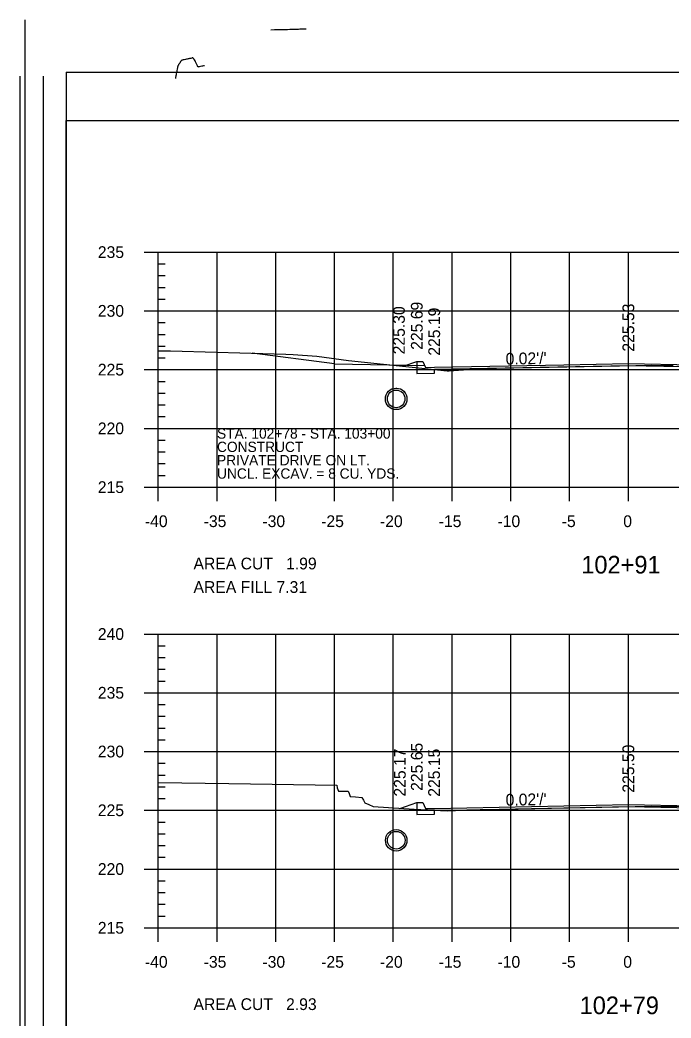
# Model space of a CAD drawing. Extents: x 1367903 to 1373764, y 376865 to 382130.
# Drawn here: x 1370213.6 to 1370324.4, y 377450.5 to 377620.4 of the extents above; entities that cross this region are included whole.
import ezdxf

# ---------------------------------------------------------------- set-up
doc = ezdxf.new("R2010")
doc.units = 0
for name, color, linetype in [('R_Axis', 7, 'Continuous'), ('R_Axis Annot', 7, 'Continuous'), ('R_Border', 7, 'Continuous'), ('R_Border PE', 7, 'Continuous'), ('R_Draft', 7, 'Continuous'), ('R_Drive', 7, 'Continuous'), ('R_Exist Surface', 7, 'Continuous'), ('R_Fin Surface', 7, 'Continuous'), ('R_Fin Surface Annot', 7, 'Continuous'), ('R_Grid', 7, 'Continuous'), ('R_Water', 7, 'Continuous')]:
    doc.layers.add(name, color=color, linetype=linetype)

msp = doc.modelspace()

# ---------------------------------------------------------------- linework, layer by layer
for points in [[(1370281.1, 377562.21), (1370281.1, 377561.54), (1370281.1, 377561.54), (1370281.1, 377560.18), (1370284.1, 377560.24), (1370284.1, 377560.91), (1370317.1, 377561.57), (1370350.1, 377560.91), (1370350.1, 377560.24), (1370353.1, 377560.18), (1370353.1, 377561.62), (1370367.1, 377561.9), (1370367.1, 377562.49)], [(1370281.1, 377487.14), (1370281.1, 377486.47), (1370281.1, 377486.47), (1370281.1, 377485.11), (1370284.1, 377485.17), (1370284.1, 377485.83), (1370317.1, 377486.49), (1370350.1, 377485.83), (1370350.1, 377485.17), (1370353.1, 377485.11), (1370353.1, 377486.55), (1370367.1, 377486.83), (1370367.1, 377487.42)]]:
    msp.add_lwpolyline(points)
at = {"layer": 'R_Axis'}
for p, q in [((1370234.7, 377580.84), (1370239.5, 377580.84)), ((1370237.1, 377540.84), (1370237.1, 377580.84)), ((1370237.1, 377578.84), (1370238.3, 377578.84)), ((1370237.1, 377576.84), (1370238.3, 377576.84)), ((1370237.1, 377574.84), (1370238.3, 377574.84)), ((1370237.1, 377572.84), (1370238.3, 377572.84)), ((1370234.7, 377570.84), (1370239.5, 377570.84)), ((1370237.1, 377568.84), (1370238.3, 377568.84)), ((1370237.1, 377566.84), (1370238.3, 377566.84)), ((1370237.1, 377564.84), (1370238.3, 377564.84)), ((1370237.1, 377562.84), (1370238.3, 377562.84)), ((1370234.7, 377560.84), (1370239.5, 377560.84)), ((1370237.1, 377558.84), (1370238.3, 377558.84)), ((1370237.1, 377556.84), (1370238.3, 377556.84)), ((1370237.1, 377554.84), (1370238.3, 377554.84)), ((1370237.1, 377552.84), (1370238.3, 377552.84)), ((1370234.7, 377550.84), (1370239.5, 377550.84)), ((1370237.1, 377548.84), (1370238.3, 377548.84)), ((1370237.1, 377546.84), (1370238.3, 377546.84)), ((1370237.1, 377544.84), (1370238.3, 377544.84)), ((1370237.1, 377538.44), (1370237.1, 377543.24)), ((1370237.1, 377542.84), (1370238.3, 377542.84)), ((1370247.1, 377538.44), (1370247.1, 377543.24)), ((1370257.1, 377538.44), (1370257.1, 377543.24)), ((1370267.1, 377538.44), (1370267.1, 377543.24)), ((1370277.1, 377538.44), (1370277.1, 377543.24)), ((1370287.1, 377538.44), (1370287.1, 377543.24)), ((1370297.1, 377538.44), (1370297.1, 377543.24)), ((1370307.1, 377538.44), (1370307.1, 377543.24)), ((1370317.1, 377538.44), (1370317.1, 377543.24)), ((1370234.7, 377540.84), (1370239.5, 377540.84)), ((1370237.1, 377540.84), (1370397.1, 377540.84)), ((1370234.7, 377515.84), (1370239.5, 377515.84)), ((1370237.1, 377465.84), (1370237.1, 377515.84)), ((1370237.1, 377513.84), (1370238.3, 377513.84)), ((1370237.1, 377511.84), (1370238.3, 377511.84)), ((1370237.1, 377509.84), (1370238.3, 377509.84)), ((1370237.1, 377507.84), (1370238.3, 377507.84)), ((1370234.7, 377505.84), (1370239.5, 377505.84)), ((1370237.1, 377503.84), (1370238.3, 377503.84)), ((1370237.1, 377501.84), (1370238.3, 377501.84)), ((1370237.1, 377499.84), (1370238.3, 377499.84)), ((1370237.1, 377497.84), (1370238.3, 377497.84)), ((1370234.7, 377495.84), (1370239.5, 377495.84)), ((1370237.1, 377493.84), (1370238.3, 377493.84)), ((1370237.1, 377491.84), (1370238.3, 377491.84)), ((1370237.1, 377489.84), (1370238.3, 377489.84)), ((1370237.1, 377487.84), (1370238.3, 377487.84)), ((1370234.7, 377485.84), (1370239.5, 377485.84)), ((1370237.1, 377483.84), (1370238.3, 377483.84)), ((1370237.1, 377481.84), (1370238.3, 377481.84)), ((1370237.1, 377479.84), (1370238.3, 377479.84)), ((1370237.1, 377477.84), (1370238.3, 377477.84)), ((1370234.7, 377475.84), (1370239.5, 377475.84)), ((1370237.1, 377473.84), (1370238.3, 377473.84)), ((1370237.1, 377471.84), (1370238.3, 377471.84)), ((1370237.1, 377469.84), (1370238.3, 377469.84)), ((1370237.1, 377463.44), (1370237.1, 377468.24)), ((1370237.1, 377467.84), (1370238.3, 377467.84)), ((1370247.1, 377463.44), (1370247.1, 377468.24)), ((1370257.1, 377463.44), (1370257.1, 377468.24)), ((1370267.1, 377463.44), (1370267.1, 377468.24)), ((1370277.1, 377463.44), (1370277.1, 377468.24)), ((1370287.1, 377463.44), (1370287.1, 377468.24)), ((1370297.1, 377463.44), (1370297.1, 377468.24)), ((1370307.1, 377463.44), (1370307.1, 377468.24)), ((1370317.1, 377463.44), (1370317.1, 377468.24)), ((1370234.7, 377465.84), (1370239.5, 377465.84)), ((1370237.1, 377465.84), (1370397.1, 377465.84))]:
    msp.add_line(p, q, dxfattribs=at)
at = {"layer": 'R_Border'}
for p, q in [((1370214.38, 377620.35), (1370214.38, 377279.12)), ((1370221.41, 377611.47), (1370425.73, 377611.47)), ((1370221.41, 377611.47), (1370221.41, 377280.59))]:
    msp.add_line(p, q, dxfattribs=at)
at = {"layer": 'R_Border PE'}
for p, q in [((1370213.57, 377610.76), (1370213.57, 377288.8)), ((1370217.49, 377610.76), (1370217.49, 377288.8)), ((1370221.41, 377603.25), (1370425.73, 377603.25)), ((1370221.41, 377288.8), (1370221.41, 377603.25))]:
    msp.add_line(p, q, dxfattribs=at)
for points in [[(1370258.26, 377618.69), (1370258.21, 377618.69), (1370257.93, 377618.68), (1370257.8, 377618.68), (1370257.73, 377618.67), (1370257.58, 377618.67), (1370257.22, 377618.66), (1370256.89, 377618.65), (1370256.26, 377618.63)], [(1370258.72, 377618.7), (1370258.26, 377618.69)], [(1370262.28, 377618.79), (1370261.93, 377618.78), (1370261.73, 377618.78), (1370261.57, 377618.77), (1370261.34, 377618.76), (1370261.19, 377618.76), (1370260.99, 377618.75), (1370260.74, 377618.75), (1370260.55, 377618.74), (1370260.27, 377618.73), (1370260.17, 377618.73), (1370260.12, 377618.73), (1370259.9, 377618.72), (1370259.8, 377618.72), (1370259.57, 377618.71), (1370259.49, 377618.72), (1370259.07, 377618.7), (1370258.83, 377618.7), (1370258.72, 377618.7)], [(1370244.96, 377612.54), (1370244.94, 377612.55), (1370244.92, 377612.55), (1370244.9, 377612.55), (1370244.88, 377612.55), (1370244.85, 377612.55), (1370244.83, 377612.55), (1370244.8, 377612.55), (1370244.66, 377612.51), (1370244.54, 377612.48), (1370244.27, 377612.41), (1370244.06, 377612.36), (1370244.03, 377612.35), (1370244.01, 377612.35), (1370243.99, 377612.34), (1370243.98, 377612.34), (1370243.97, 377612.35), (1370243.94, 377612.35), (1370243.92, 377612.36), (1370243.9, 377612.38), (1370243.88, 377612.39), (1370243.86, 377612.4), (1370243.84, 377612.42), (1370243.82, 377612.45), (1370243.81, 377612.47), (1370243.79, 377612.5), (1370243.77, 377612.55), (1370243.68, 377612.76), (1370243.57, 377613), (1370243.46, 377613.23), (1370243.45, 377613.26), (1370243.44, 377613.28), (1370243.4, 377613.34), (1370243.37, 377613.39), (1370243.25, 377613.57), (1370243.17, 377613.69), (1370243.14, 377613.74), (1370243.13, 377613.76), (1370243.11, 377613.78), (1370243.09, 377613.81), (1370243.07, 377613.83), (1370243.06, 377613.84), (1370243.04, 377613.85), (1370243.01, 377613.87), (1370243, 377613.87), (1370242.97, 377613.88), (1370242.94, 377613.88), (1370242.93, 377613.88), (1370242.89, 377613.88), (1370242.79, 377613.86), (1370242.62, 377613.82), (1370242.42, 377613.77), (1370242.28, 377613.74), (1370242.17, 377613.72), (1370242.03, 377613.69), (1370241.91, 377613.66), (1370241.74, 377613.63), (1370241.52, 377613.58), (1370241.47, 377613.57), (1370241.35, 377613.54), (1370241.23, 377613.52), (1370241.19, 377613.51), (1370241.16, 377613.5), (1370241.14, 377613.5), (1370241.13, 377613.49), (1370241.11, 377613.49), (1370241.09, 377613.47), (1370241.07, 377613.46), (1370241.05, 377613.44), (1370241.03, 377613.42), (1370241, 377613.39), (1370240.97, 377613.35), (1370240.94, 377613.31), (1370240.9, 377613.26), (1370240.84, 377613.16), (1370240.75, 377613.02), (1370240.67, 377612.89), (1370240.57, 377612.75), (1370240.52, 377612.67), (1370240.48, 377612.62), (1370240.45, 377612.55), (1370240.44, 377612.54), (1370240.43, 377612.52), (1370240.42, 377612.5), (1370240.41, 377612.48), (1370240.41, 377612.46), (1370240.4, 377612.44), (1370240.39, 377612.42), (1370240.39, 377612.39), (1370240.38, 377612.37), (1370240.38, 377612.35), (1370240.37, 377612.33), (1370240.36, 377612.24), (1370240.32, 377612), (1370240.27, 377611.76), (1370240.25, 377611.65), (1370240.17, 377611.18), (1370240.14, 377611.04), (1370240.1, 377610.84), (1370240.05, 377610.54), (1370240.02, 377610.39)]]:
    msp.add_lwpolyline(points, dxfattribs=at)
at = {"layer": 'R_Drive'}
for q in [(1370253.1, 377563.66), (1370282.44, 377561.54)]:
    msp.add_line((1370267.11, 377561.85), q, dxfattribs=at)
at = {"layer": 'R_Exist Surface'}
for points in [[(1370237.1, 377564.05), (1370239.21, 377564.02), (1370247.05, 377563.83), (1370258.81, 377563.49), (1370260.07, 377563.41), (1370264.09, 377563.14), (1370269.5, 377562.42), (1370286.24, 377560.66), (1370286.45, 377560.64), (1370286.56, 377560.64), (1370286.61, 377560.64), (1370289.82, 377560.88), (1370290.99, 377560.99), (1370291.65, 377561.04), (1370315.6, 377561.51), (1370321.08, 377561.61), (1370324.71, 377561.57)], [(1370237.1, 377490.54), (1370249.13, 377490.38), (1370267.48, 377490.09), (1370267.55, 377489.68), (1370267.77, 377489.1), (1370268.52, 377489.09), (1370269.4, 377489.07), (1370269.59, 377488.67), (1370269.74, 377488.18), (1370270.66, 377488.13), (1370271.74, 377488), (1370272.03, 377487.56), (1370272.27, 377487.1), (1370272.92, 377486.85), (1370273.66, 377486.46), (1370280.67, 377486.02), (1370286.26, 377485.74), (1370291.9, 377485.99), (1370292.12, 377485.99), (1370292.18, 377485.99), (1370292.28, 377485.99), (1370292.68, 377486), (1370321.12, 377486.53), (1370337.44, 377486.35)]]:
    msp.add_lwpolyline(points, dxfattribs=at)
at = {"layer": 'R_Fin Surface'}
for points in [[(1370278.8, 377561.44), (1370281.1, 377562.21), (1370282.1, 377562.21), (1370282.6, 377561.21), (1370284.1, 377561.24), (1370306.1, 377561.68), (1370317.1, 377561.9), (1370328.1, 377561.68), (1370350.1, 377561.24), (1370351.6, 377561.21), (1370352.1, 377562.21), (1370353.1, 377562.21), (1370357.1, 377562.29), (1370367.1, 377562.49), (1370374.27, 377560.1)], [(1370278.21, 377486.17), (1370281.1, 377487.14), (1370282.1, 377487.14), (1370282.6, 377486.14), (1370284.1, 377486.17), (1370306.1, 377486.61), (1370317.1, 377486.83), (1370328.1, 377486.61), (1370350.1, 377486.17), (1370351.6, 377486.14), (1370352.1, 377487.14), (1370353.1, 377487.14), (1370357.1, 377487.22), (1370367.1, 377487.42), (1370372.69, 377485.56)]]:
    msp.add_lwpolyline(points, dxfattribs=at)
at = {"layer": 'R_Grid'}
for p, q in [((1370237.1, 377580.84), (1370397.1, 377580.84)), ((1370237.1, 377540.84), (1370237.1, 377580.84)), ((1370247.1, 377540.84), (1370247.1, 377580.84)), ((1370257.1, 377540.84), (1370257.1, 377580.84)), ((1370267.1, 377540.84), (1370267.1, 377580.84)), ((1370277.1, 377540.84), (1370277.1, 377580.84)), ((1370287.1, 377540.84), (1370287.1, 377580.84)), ((1370297.1, 377540.84), (1370297.1, 377580.84)), ((1370307.1, 377540.84), (1370307.1, 377580.84)), ((1370317.1, 377540.84), (1370317.1, 377580.84)), ((1370237.1, 377570.84), (1370397.1, 377570.84)), ((1370237.1, 377560.84), (1370397.1, 377560.84)), ((1370237.1, 377550.84), (1370397.1, 377550.84)), ((1370237.1, 377540.84), (1370397.1, 377540.84)), ((1370237.1, 377515.84), (1370397.1, 377515.84)), ((1370237.1, 377465.84), (1370237.1, 377515.84)), ((1370247.1, 377465.84), (1370247.1, 377515.84)), ((1370257.1, 377465.84), (1370257.1, 377515.84)), ((1370267.1, 377465.84), (1370267.1, 377515.84)), ((1370277.1, 377465.84), (1370277.1, 377515.84)), ((1370287.1, 377465.84), (1370287.1, 377515.84)), ((1370297.1, 377465.84), (1370297.1, 377515.84)), ((1370307.1, 377465.84), (1370307.1, 377515.84)), ((1370317.1, 377465.84), (1370317.1, 377515.84)), ((1370237.1, 377505.84), (1370397.1, 377505.84)), ((1370237.1, 377495.84), (1370397.1, 377495.84)), ((1370237.1, 377485.84), (1370397.1, 377485.84)), ((1370237.1, 377475.84), (1370397.1, 377475.84)), ((1370237.1, 377465.84), (1370397.1, 377465.84))]:
    msp.add_line(p, q, dxfattribs=at)
at = {"layer": 'R_Water'}
for p, q in [((1370277.59, 377557.72), (1370277.59, 377557.67)), ((1370277.59, 377557.39), (1370277.59, 377557.34)), ((1370277.59, 377554.39), (1370277.59, 377554.34)), ((1370277.59, 377554.05), (1370277.59, 377554.01)), ((1370277.6, 377482.59), (1370277.6, 377482.54)), ((1370277.6, 377482.25), (1370277.6, 377482.21)), ((1370277.6, 377479.25), (1370277.6, 377479.21)), ((1370277.6, 377478.92), (1370277.6, 377478.87))]:
    msp.add_line(p, q, dxfattribs=at)
for centre, radius in [((1370277.59, 377555.86), 1.83), ((1370277.59, 377555.86), 1.5), ((1370277.6, 377480.73), 1.83), ((1370277.6, 377480.73), 1.5)]:
    msp.add_circle(centre, radius, dxfattribs=at)

# ---------------------------------------------------------------- texts
at = {"layer": 'R_Axis Annot'}
for s, height, p in [('235', 2, (1370226.82, 377579.84)), ('230', 2, (1370226.82, 377569.84)), ('225', 2, (1370226.82, 377559.84)), ('220', 2, (1370226.82, 377549.84)), ('215', 2, (1370226.82, 377539.84)), ('-40', 2, (1370234.83, 377534.04)), ('-35', 2, (1370244.83, 377534.04)), ('-30', 2, (1370254.83, 377534.04)), ('-25', 2, (1370264.83, 377534.04)), ('-20', 2, (1370274.83, 377534.04)), ('-15', 2, (1370284.83, 377534.04)), ('-10', 2, (1370294.83, 377534.04)), ('-5', 2, (1370305.76, 377534.04)), ('0', 2, (1370316.23, 377534.04)), ('AREA CUT   1.99', 2, (1370243.1, 377526.84)), ('102+91', 3, (1370309.09, 377526.14)), ('AREA FILL 7.31', 2, (1370243.1, 377522.84)), ('240', 2, (1370226.82, 377514.84)), ('235', 2, (1370226.82, 377504.84)), ('230', 2, (1370226.82, 377494.84)), ('225', 2, (1370226.82, 377484.84)), ('220', 2, (1370226.82, 377474.84)), ('215', 2, (1370226.82, 377464.84)), ('-40', 2, (1370234.83, 377459.04)), ('-35', 2, (1370244.83, 377459.04)), ('-30', 2, (1370254.83, 377459.04)), ('-25', 2, (1370264.83, 377459.04)), ('-20', 2, (1370274.83, 377459.04)), ('-15', 2, (1370284.83, 377459.04)), ('-10', 2, (1370294.83, 377459.04)), ('-5', 2, (1370305.76, 377459.04)), ('0', 2, (1370316.23, 377459.04)), ('AREA CUT   2.93', 2, (1370243.1, 377451.84)), ('102+79', 3, (1370308.81, 377451.14))]:
    msp.add_text(s, height=height, dxfattribs=at).set_placement(p)
at = {"layer": 'R_Draft'}
for s, p in [('STA. 102+78 - STA. 103+00', (1370247.1, 377549.09)), ('CONSTRUCT', (1370247.1, 377546.82)), ('PRIVATE DRIVE ON LT.', (1370247.1, 377544.55)), ('UNCL. EXCAV. = 8 CU. YDS.', (1370247.1, 377542.28))]:
    msp.add_text(s, height=1.75, dxfattribs=at).set_placement(p)
at = {"layer": 'R_Fin Surface Annot'}
for s, rotation, p in [('225.30', 90, (1370279.06, 377563.44)), ('225.69', 90, (1370282.1, 377564.21)), ('225.19', 90, (1370285.06, 377563.21)), ('225.53', 90, (1370318.1, 377563.9)), ("0.02'/'", 1.1458, (1370296.23, 377561.68)), ('225.17', 90, (1370279.21, 377488.17)), ('225.65', 90, (1370282.1, 377489.14)), ('225.15', 90, (1370285.04, 377488.14)), ('225.50', 90, (1370318.1, 377488.83)), ("0.02'/'", 1.1458, (1370296.23, 377486.61))]:
    msp.add_text(s, height=2, rotation=rotation, dxfattribs=at).set_placement(p)

doc.saveas('drawing.dxf')
